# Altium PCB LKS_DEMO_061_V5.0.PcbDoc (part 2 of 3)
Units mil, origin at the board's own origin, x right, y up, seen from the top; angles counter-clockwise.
Board outline 4534.65 x 3225.59 mil, 2 copper layers (Top Layer, Bottom Layer); 196 components, 108 nets, 502 pads, 1380 vias.
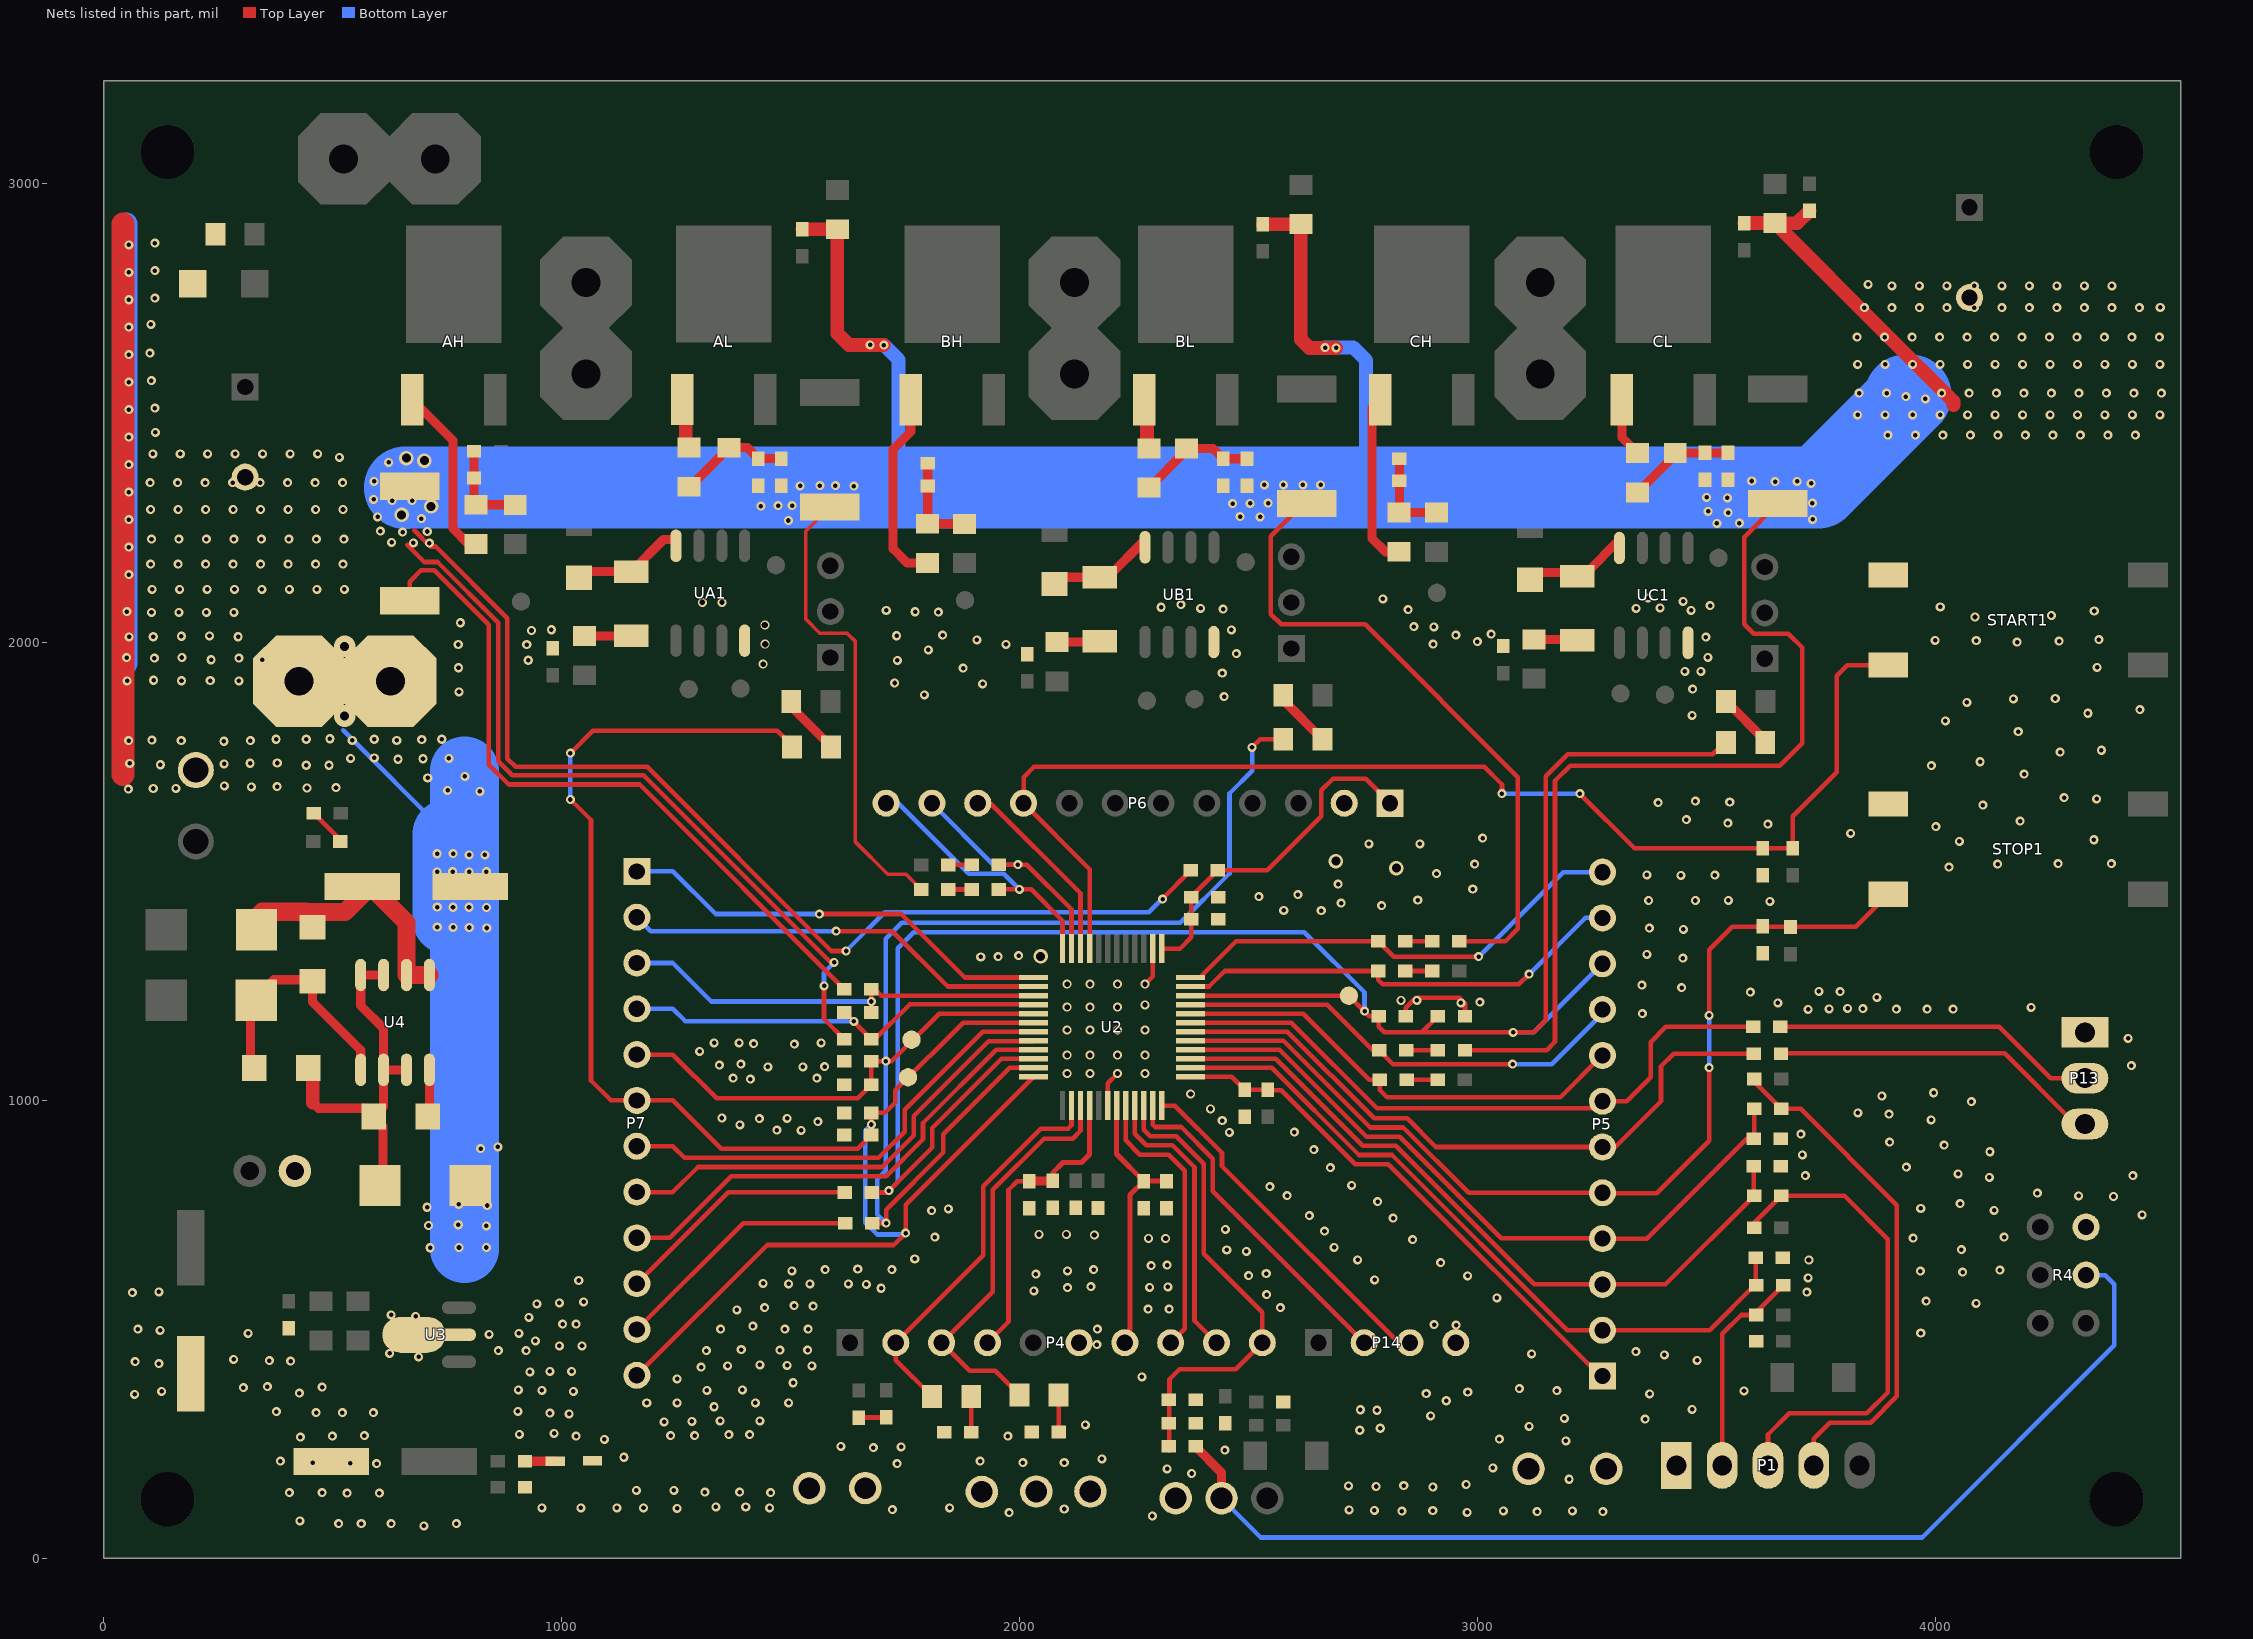
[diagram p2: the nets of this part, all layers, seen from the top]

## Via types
v1: diameter 19.68, hole 9.84, Top Layer to Bottom Layer, 1169 vias
v2: diameter 20, hole 10, Top Layer to Bottom Layer, 156 vias
v3: diameter 19.68, hole 11.81, Top Layer to Bottom Layer, 34 vias
v4: diameter 47.24, hole 20, Top Layer to Bottom Layer, 10 vias
v5: diameter 31.5, hole 19.68, Top Layer to Bottom Layer, 7 vias
v6: diameter 19.68, hole 13.78, Top Layer to Bottom Layer, 2 vias
v7: diameter 23.62, hole 11.81, Top Layer to Bottom Layer, 2 vias

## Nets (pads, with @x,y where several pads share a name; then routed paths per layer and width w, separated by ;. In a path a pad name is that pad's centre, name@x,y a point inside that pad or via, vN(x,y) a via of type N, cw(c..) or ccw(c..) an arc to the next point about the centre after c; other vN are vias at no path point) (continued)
GND: AGND.1 C1.2 C2.1 C3.2 C6.1 C12.2 C13.2 C14.2 C15.1 C17.1 C18.2 C19.1 C21.2 C22.1 C23.1 C25.1 C26.1 C27.1 C28.2 C29.2 C30.2 C31.2 C32.2 C33.2 C36.2 C37.1 C43.1 C44.1 C45.1 CA-5.1 CC3.2 CF1.2 D02.1 DM_IN.2 G1.1 G2.1 G3.1 G4.1 G5.1 G6.1 G7.1 G8.1 LED.2 P1.1 P4.6 P6.2 P13.1 P14.4 R4.2 R10.2 R14.2 R20.1 R43.1 R56.2 R58.2 R60.2 R69.2 R76.1 RA-5.2 RT-1.1 START1.1 STOP1.1 U2.6 U2.26 U3.2 UA1.4 UB1.4 UC1.4 | length 5737.3
  Top Layer w10: R69.2@668.11,2090.16 668.11,2132.05 692.99,2156.93 721.73,2156.93 840.94,2037.71 840.94,1732.28 884.25,1688.98 1170.55,1688.98 RT-1.1@1617.32,1242.2 ; RT-1.1@1619.29,1236.94 RT-1.1@1619.29,1251.26 ; R76.1@1648.43,307.31 C44.1@1709.05,307.31 ; U2.6@2191.84,988.17 2191.84,1036.6 v3(2213.41,1058.17) ; v3(2273.41,1253.17) 2290.26,1270.02 U2.26@2290.26,1330.69 ; P6.2@2708.41,1625.02 P6.2@2708.41,1648.17 ; R60.2@2842.91,1183.54 2842.91,1202.05 2864.57,1223.7 2960.16,1223.7 2972.05,1211.81 C18.2@2972.05,1183.07
  Top Layer w50: 42.52,1710.63 42.52,2912.97
  Bottom Layer w10: 523.23,1807.09 749.21,1581.1 ; P6.2@2702.41,1640.28 P6.2@2702.41,1654.17
  Bottom Layer w50: 49.61,1953.15 49.61,2912.4
  Bottom Layer w150: 749.21,1393.7 749.21,1581.1 ; 787.8,675.34 787.8,1719.17
  other v1: 699.21,70.87 512.99,75.59 562.6,75.59 627.95,75.59 770.47,75.59 428.74,81.5 1976.77,99.61 2976.77,100 3129.53,101.57 3272.83,101.57 3055.91,103.15 3206.69,103.15 2718.9,105.51 2774.41,104.72 1722.05,106.3 2097.24,107.48 1252.36,108.66 956.69,109.84 1042.13,109.84 1120.47,109.84 1178.74,109.84 1453.94,109.84 1846.85,109.84 1336.61,112.2 1401.97,112.2 531.89,142.13 601.97,142.13 405.91,143.31 477.17,143.31 1456.3,143.31 1312.6,144.49 1388.58,144.49 1163.39,148.03 1245.28,148.03 3199.61,172.44 2321.65,195.28 3033.07,197.24 596.06,206.3 538.98,207.48 1732.4,206.69 457.09,208.66 2007.09,208.66 2097.24,208.66 385.83,212.2 1913.39,212.2 2179.13,216.93 1135.83,220.47 2448.03,236.22 1680.71,241.73 1741.34,242.91 1609.45,244.09 3192.52,256.3 1093.31,259.45 3047.24,259.84 429.92,264.17 499.61,266.54 1031.5,266.54 1974.02,266.54 569.68,267.72 1238.19,267.72 1290.16,267.72 907.87,270.47 1364.96,270.08 1410.24,270.08 983.86,272.44 3112.2,287.8 2143.31,291.34 1223.62,297.64 1284.25,298.82 1346.06,300 1432.68,300 3365.35,303.54 3189.03,305.21 1016.14,315.35 974.41,316.54 464.17,317.72 521.26,317.72 588.98,317.72 377.56,320.08 904.72,320.47 3468.11,324.8 1333.07,330.71 1185.83,338.98 1252.36,338.98 1423.23,338.98 1495.67,338.98 67.72,357.87 3375.2,359.06 427.56,360.63 126.58,364.25 1025.59,364.17 3581.1,365.35 956.69,366.54 1317.32,366.54 3172.44,365.75 905.51,367.72 1394.49,367.72 3090.94,370.08 305.12,372.44 477.17,373.62 357.48,374.8 1505.12,383.07 1252.36,391.34 2266.93,396.06 930.71,406.69 974.41,407.87 1022.05,407.87 1304.33,417.32 1362.6,419.69 1546.46,419.69 1492.13,420.87 1432.68,422.05 120.83,424.62 68.9,429.13 408.27,430.31 362.2,431.5 3478.74,431.89 283.86,433.86 687.8,439.37 3407.09,444.09 3117.72,446.06 624.41,447.24 3344.88,450.79 861.81,453.15 922.44,453.15 1316.14,453.15 1476.38,454.33 1537.01,454.33 1392.13,455.51 994.88,463.78 1044.49,463.78 2168.5,466.14 942.52,474.41 841.73,488.58 315.75,490.94 906.69,490.94 3966.93,491.34 123.71,497.63 74.8,500.39 1347.24,500.39 1487.4,500.39 1538.19,500.39 2169.68,500.39 1417.32,506.69 2952.76,508.66 2904.72,509.84 1001.97,511.02 1031.5,511.02 928.35,525.59 681.5,527.95 627.95,531.5 1382.68,542.13 2280.31,543.7 2325.98,543.7 1443.31,546.85 2568.9,547.24 1548.82,550.39 1507.48,551.57 946.06,555.12 4087.8,556.3 994.88,557.48 1048.03,559.84 3978.74,561.02 3041.73,568.5 2538.98,575.59 62.99,579.92 120.83,581.57 3718.5,580.71 2030.71,583.46 1697.24,589.37 2104.33,590.55 2283.46,591.34 2323.23,592.13 2155.51,592.91 1665.35,597.64 1495.67,598.82 1541.73,598.82 1625.98,598.82 1439.76,600 1037.4,606.3 2774.8,607.87 3720.87,611.81 2977.95,616.54 2499.61,616.93 2035.43,620.47 2538.19,621.26 4058.27,624.8 1502.76,627.56 2104.33,627.56 3966.14,626.77 4139.76,628.74 1575.2,629.92 1720.87,629.92 2161.42,629.92 1646.46,631.1 2286.61,638.98 2321.65,639.76 2918.9,645.28 2737.4,651.18 1770.87,653.54 2494.88,669.69 2451.97,673.23 4055.51,673.62 2686.22,678.74 2857.87,695.67 3950.39,698.82 1814.96,701.18 4148.82,700.79 2665.35,714.17 2449.21,718.11 2815.35,742.52 2632.28,748.03 4449.99,749.41 1807.87,759.06 4127.17,759.45 1844.49,762.6 3966.93,763.78 4052.76,774.02 2781.1,778.35 4387.72,789.66 2583.86,791.34 4311.77,791.17 4221.4,797.25 2546.06,811.42 2724.41,814.17 4116.93,831.5 3714.96,835.43 4430.24,835.22 4048.43,838.98 2677.95,852.76 3935.83,853.54 3708.66,880.31 4117.85,887.37 2642.13,892.13 823.23,894.09 861.02,898.03 4018.11,901.97 3899.21,908.27 3705.12,925.59 2457.48,929.53 2599.61,930.31 1470.08,934.65 1522.83,933.86 1389.37,946.06 1559.45,953.15 2442.13,955.51 3989.36,957.1 1431.5,959.84 1492.52,960.24 1350,961.02 3897.64,969.69 3829.92,972.44 4077.56,996.85 3881.89,1009.06 3995.28,1016.14 1411.81,1046.06 1374.41,1048.03 1557.48,1048.03 1450,1072.44 1526.77,1072.44 1574.02,1073.23 4426.77,1075.59 1344.49,1076.38 1391.34,1078.74 1301.18,1106.69 1508.27,1122.44 1419.29,1123.62 1333.07,1124.8 1387.4,1124.8 1566.54,1124.8 4419.68,1135.04 3359.06,1188.98 3720.85,1197.99 3913.8,1198.51 3980.71,1198.51 4037.78,1198.55 3767.02,1199.03 3840.67,1199.55 3807.07,1200.12 4207.89,1202.66 2962.99,1212.6 3654.98,1212.52 3004.33,1214.17 2866.93,1217.72 3871.19,1224.3 3594.88,1235.83 3744.53,1237.43 3790.99,1236.72 3444.88,1245.67 3358.27,1251.18 3447.64,1309.84 1914.96,1312.99 1952.76,1313.39 1997.64,1315.35 3369.29,1318.11 3448.82,1372.83 3374.41,1375.59 2576.38,1414.17 2658.27,1413.78 2790.16,1424.8 2701.57,1430.31 3637.8,1433.86 2868.9,1436.61 3372.83,1435.83 3475.2,1435.83 3546.85,1436.22 2522.05,1444.09 2607.09,1448.43 2988.98,1460.63 2695.28,1471.65 3443.31,1490.55 3517.72,1491.34 3369.29,1491.73 2909.84,1494.49 728.47,1498.5 798.12,1498.32 762.2,1498.95 835.86,1498.95 4028.62,1508.49 2993.31,1515.35 4134.6,1515.43 4266.65,1516.31 4383.07,1516.14 798.27,1535.5 832.28,1535.43 728.19,1537.87 763.23,1538.24 2762.2,1559.45 2873.62,1559.45 3010.63,1572.05 3813.78,1582.28 3999.95,1597.1 3633.46,1602.76 3545.67,1604.72 4184.12,1609.26 3455.12,1612.2 4102.46,1644.01 3393.7,1649.61 3550,1650.79 3474.98,1652.75 4350.91,1657.91 4279.67,1660.51 750.96,1676.16 789.03,1706.67 4192.8,1711.76 3990.4,1730.01 4096.38,1738.7 4270.99,1759.55 54.75,1784.96 4179.78,1804.72 4020.8,1828.17 3468.11,1840.16 4445.55,1852.55 4067.71,1868.13 4169.35,1875.95 2446.06,1880.71 1792.13,1884.65 3468.9,1897.24 1918.9,1908.66 1726.77,1910.63 2442.13,1932.28 3451.97,1935.83 3487.01,1935.83 1876.38,1942.91 4352.05,1944.67 1733.07,1959.84 50.4,1965.95 3502.36,1966.54 2473.23,1974.8 1800.39,1982.68 1970.08,1994.88 2902.36,1995.28 2998.82,2001.18 4269.03,2002.25 3998.54,2003.89 1906.3,2004.72 4355.79,2005.53 55.71,2011.55 3497.64,2011.02 1731.5,2013.78 1831.89,2015.35 2952.36,2015.35 3029.13,2017.32 2461.81,2026.77 2904.33,2033.07 2860.24,2033.86 104.72,2064.96 164.72,2064.96 224.72,2064.96 284.72,2064.96 1822.44,2065.35 50.91,2066.28 1771.65,2066.14 1708.66,2069.29 3465.75,2069.29 2444.09,2071.65 2847.64,2070.87 2394.88,2073.62 3345.67,2073.62 3398.03,2074.41 2308.66,2075.98 3507.09,2079.53 2351.57,2081.5 3448.43,2088.98 2792.91,2094.09 3372.05,2096.46 105.91,2114.96 165.91,2114.96 225.91,2114.96 285.91,2114.96 345.91,2114.96 405.91,2114.96 465.91,2114.96 525.91,2114.96 55.51,2147.24 102.76,2170.08 162.76,2170.08 222.76,2170.08 282.76,2170.08 342.76,2170.08 402.76,2170.08 462.76,2170.08 522.76,2170.08 55.51,2207.24 104.72,2224.8 164.72,2224.8 224.72,2224.8 284.72,2224.8 344.72,2224.8 404.72,2224.8 464.72,2224.8 524.72,2224.8 55.51,2267.24 102.76,2289.37 162.76,2289.37 222.76,2289.37 282.76,2289.37 342.76,2289.37 402.76,2289.37 462.76,2289.37 522.76,2289.37 55.51,2327.24 101.97,2348.03 161.97,2348.03 221.97,2348.03 281.97,2348.03 341.97,2348.03 401.97,2348.03 461.97,2348.03 521.97,2348.03 55.51,2387.24 514.96,2403.15 107.48,2410.63 167.48,2410.63 227.48,2410.63 287.48,2410.63 347.48,2410.63 407.48,2410.63 467.48,2410.63 55.51,2447.24 112.99,2457.48 55.51,2507.24 112.2,2510.71 55.51,2567.24 104.38,2570.53 55.51,2627.24 101.44,2630.72 55.51,2687.24 103.47,2693.4 55.51,2747.24 112.2,2750.71 55.51,2807.24 112.2,2810.71 55.51,2867.24 112.2,2870.71
  other v2: 2289.76,92.13 2834.25,102.76 2901.57,103.94 2901.97,155.51 2777.95,156.69 2717.72,157.87 2838.19,158.66 2974.41,161.02 2375.2,185.04 2742.13,279.53 2787.01,283.86 2896.85,310.63 2779.92,323.23 2743.7,324.02 2931.1,343.7 2887.4,359.45 2977.95,362.6 712.99,677.95 775.98,678.35 835.83,678.35 835.83,725.59 709.45,726.38 774.41,727.95 706.3,766.14 837.8,770.08 775.59,772.83 836.59,1375.81 763.23,1377.1 798.45,1376.91 728.56,1377.82 836.05,1420.53 728.38,1421.44 762.87,1421.26 797.9,1421.07 4051.2,1564.95 4344.83,1568.43 821.66,1674.05 54.39,1678.91 108.42,1680.3 157.92,1680.65 444.09,1681.5 507.48,1682.28 322.8,1683.79 378.92,1684.48 263.89,1685.88 707.76,1703.35 442.52,1731.1 492.13,1731.1 124.1,1732.24 263.19,1733.99 57.18,1735.03 320.01,1735.37 379.27,1736.07 642.81,1744.14 697.49,1745.35 539.37,1746.06 753.98,1745.95 590.94,1747.24 4361.34,1763.89 262.84,1783.48 169.77,1784.88 320.71,1784.88 542.91,1785.43 640.16,1785.43 105.64,1785.92 694.77,1787.04 376.77,1787.8 442.52,1787.8 590.94,1787.8 738.27,1787.94 494.09,1788.98 4331.8,1844.68 4260.56,1876.82 775.96,1891.09 51.52,1915.15 170.3,1915.52 295.44,1915.15 109.41,1916.64 233.05,1915.89 774.95,1943.93 927.17,1960.24 234.92,1961.47 346.46,1961.81 110.91,1964.83 295.44,1964.83 171.05,1966.32 924.02,1994.49 774.44,1994.74 4177.37,1999.8 4088.16,2003.07 108.52,2011.55 293.82,2011.55 169.97,2012.51 231.42,2013.47 934.25,2025.2 977.56,2026.77 779.01,2041.99 4085.29,2054.63 4252.26,2057.91 4345.56,2067.73 4009.59,2076.73
  other v3: 3722.6,651.06 2281.1,698.43 2318.5,698.03 2162.99,705.59 2042.13,707.17 2101.97,707.17 2416.54,981.1 2373.23,1013.39 2103.41,1058.17 2153.41,1058.17 2273.41,1058.17 2103.41,1098.17 2153.41,1098.17 2213.41,1098.17 2273.41,1098.17 2103.41,1153.17 2153.41,1153.17 2213.41,1153.17 2273.41,1153.17 2103.41,1203.17 2153.41,1203.17 2213.41,1203.17 2273.41,1208.17 2832.28,1217.72 2103.41,1253.17 2153.41,1253.17 2213.41,1253.17 1439.76,1951.57 1307.11,2086.72 1350.11,2086.72
  other v4: 526.38,1838.57 526.38,1990.57
  other v5: 2045.67,1313.78 2822.05,1506.3 2690.16,1521.65
  other v6: 1444.49,1995.28 1443.7,2037.4
HALL_A: C31.1 P5.4 R54.2 U2.16 | length 1555.5
  Top Layer w10: U2.16@2372.94,1110.22 2567.15,1110.22 2757.14,920.24 2829.26,920.24 3051.07,698.43 3271.34,698.43 P5.4@3272.05,697.72 3368.47,697.72 3586.81,916.06 C31.1@3602.6,916.06 ; C31.1@3603.07,916.54 R54.2@3603.07,981.06
HALL_B: C32.1 P5.3 R57.2 U2.15 | length 1578.9
  Top Layer w10: U2.15@2372.94,1090.54 2558.55,1090.54 2748.85,900.24 2820.98,900.24 3123.5,597.72 P5.3@3272.05,597.72 3409.72,597.72 R57.2@3603.07,791.06 ; R57.2@3602.6,791.54 C32.1@3602.6,856.06
HALL_C: C33.1 P5.2 R62.2 U2.14 | length 1570.5
  Top Layer w10: U2.14@2372.94,1070.85 2549.95,1070.85 2740.57,880.24 2812.69,880.24 3195.21,497.72 P5.2@3272.05,497.72 3506.18,497.72 3606.3,597.83 C33.1@3606.3,656.06
LDO15: C27.2 C28.1 P4.7 U2.7 | length 604.3
  Top Layer w11: U2.7@2211.52,988.17 2211.52,882.58 C27.2@2270.87,823.23 ; P4.7@2240.94,470.47 2240.94,793.31 C27.2@2270.87,823.23 ; C28.1@2320.47,823.23 C27.2@2270.87,823.23
LDO33: C29.1 C30.1 P4.4 U2.4 | length 678.5
  Top Layer w10: P4.4@1929.53,470.47 1975.59,516.54 1975.59,803.94 1994.91,823.25 C29.1@2020.58,823.25
  Top Layer w11: C30.1@2072.44,824.02 2072.44,841.73 2094.49,863.78 2135.04,863.78 2152.47,881.21 U2.4@2152.47,988.17
  Top Layer w20: C29.1@2020.58,823.25 C30.1@2072.44,823.25
LED2: L2.1 P4.2 U2.2 | length 861
  Top Layer w10: L2.1@1808.43,353.51 1729.53,432.41 P4.2@1729.53,470.47 1920.47,661.42 1920.47,811.81 2046.06,937.4 2105.51,937.4 2113.1,944.99 U2.2@2113.1,988.17
LED3: L1.1 P4.3 U2.3 | length 897.4
  Top Layer w10: L1.1@1999.41,356.29 1946.25,409.45 1890.55,409.45 P4.3@1829.53,470.47 1940.94,581.89 1940.94,804 2053.09,916.14 2116.14,916.14 2132.78,932.78 U2.3@2132.78,988.17
LKS_PIN7: P6.10 U2.34 | length 426.6
  Top Layer w10: P6.10@1908.41,1648.17 1936.08,1648.17 2132.78,1451.47 U2.34@2132.78,1330.69
LKS_PIN8: P7.1 U2.37 | length 962.1
  Top Layer w10: v1(1562.6,1406.3) 1741.34,1406.3 1879.94,1267.7 U2.37@2030.42,1267.7
  Bottom Layer w10: P7.1@1164.25,1499.39 1242.99,1499.39 1336.09,1406.3 v1(1562.6,1406.3)
LKS_PIN10: P4.9 U2.9 | length 625.4
  Top Layer w10: U2.9@2250.89,988.17 2250.89,926.28 2275.91,901.26 2333.45,901.26 2381.5,853.21 2381.5,518.5 P4.9@2429.53,470.47
LKS_PIN11: P4.8 U2.8 | length 620.8
  Top Layer w10: U2.8@2231.21,988.17 2231.21,912.2 2262.31,881.1 2325.32,881.1 2360.24,846.19 2360.24,501.18 P4.8@2329.53,470.47
NetAH_1: AH.1 K1.2 | length 382.5
  Top Layer w20: AH.1@673.62,2529.13 762.6,2440.16 762.6,2248.03 796.65,2213.98 K1.2@812.99,2213.98
NetAL_1: AL.1 K2.2 | length 112.7
  Top Layer w20: AL.1@1258.27,2529.13 AL.1@1270.87,2516.54
  Top Layer w30: AL.1@1270.87,2516.54 1270.87,2431.69 K2.2@1277.95,2424.61
NetBH_1: BH.1 K3.2 | length 429.6
  Top Layer w20: BH.1@1762.2,2529.13 1762.2,2459.45 1723.62,2420.87 1723.62,2203.54 1754.53,2172.64 K3.2@1798.82,2172.64
NetBL_1: BL.1 K4.2 | length 67.8
  Top Layer w30: K4.2@2277.95,2422 BL.1@2277.95,2489.76
NetC7_1: C7.1 K1.1 K+A1.2 R21.2 | length 204.2
  Top Layer w20: C7.1@808.72,2358.14 R21.2@808.66,2416.14 ; C7.1@808.72,2358.14 808.72,2303.88 K1.1@812.99,2299.61 898.62,2299.61 K+A1.2@898.82,2299.41
NetC11_1: C11.1 K2.1 K-A1.1 R31.2 | length 246.9
  Top Layer w20: K2.1@1277.95,2338.98 1280.31,2338.98 K-A1.1@1365.35,2424.02 ; K-A1.1@1365.35,2424.8 1405.23,2424.8 R31.2@1429.56,2400.47 1429.64,2400.39 C11.1@1479.53,2400.39
NetC16_1: C16.1 K3.1 K+B1.2 R39.2 | length 212.8
  Top Layer w20: R39.2@1799.21,2390.16 1799.21,2258.66 K3.1@1798.82,2258.27 1879.33,2258.27 K+B1.2@1879.53,2258.07
NetC20_1: C20.1 K4.1 K-B1.1 R45.2 | length 261.3
  Top Layer w20: K4.1@2282.39,2337.06 2364.17,2418.84 K-B1.1@2364.17,2422.83 2421.65,2422.83 R45.2@2444.49,2400 2496.12,2400 C20.1@2496.28,2399.84
NetC24_1: C24.1 K5.1 K+C1.2 R50.2 | length 200
  Top Layer w20: R50.2@2828.74,2400 2828.74,2283.46 K5.1@2827.95,2282.68 2828.15,2282.48 K+C1.2@2910.24,2282.48
NetC34_1: C34.1 K6.1 K-C1.1 R63.2 | length 232.8
  Top Layer w20: K6.1@3349.02,2326.73 3435.33,2413.05 C34.1@3546.09,2413.05
NetCAH1_1: CAH1.1 D1.2 UA1.8 | length 240.8
  Top Layer w20: CAH1.1@1037.8,2153.94 1151.39,2153.94 D1.2@1151.93,2153.4 1222.45,2223.93 UA1.8@1249.14,2223.93
NetCBH1_1: CBH1.1 D2.2 UB1.8 | length 230.6
  Top Layer w20: CBH1.1@2076.77,2141.34 2192.21,2141.34 UB1.8@2273.62,2222.75
NetCCH1_1: CCH1.1 D4.2 UC1.8 | length 225.3
  Top Layer w20: CCH1.1@3113.39,2151.57 3237.49,2151.57 UC1.8@3309.06,2223.14
NetCF1_1: CF1.1 DD6.2 RP1.2 U4.5 U4.6 | length 567.4
  Top Layer w40: DD6.2@321.98,1386.47 346.53,1411.02 440.94,1411.02 ; 441.34,1410.63 527.17,1410.63 582.68,1466.14 661.42,1387.4 ; 661.42,1385.74 U4.6@661.42,1273.14 U4.5@711.42,1273.14
NetCF2_1: CF2.1 DP1.2 RP1.1 U4.1 | length 538
  Top Layer w20: CF2.1@320.8,1067.05 320.8,1211.6 372,1262.8 RP1.1@455.94,1262.8 ; RP1.1@455.84,1259.49 455.84,1214.65 561.42,1109.07 U4.1@561.42,1066.14
NetCF2_2: CF2.2 D02.2 PL1.2 RP2.2 U4.2 U4.3 U4.7 U4.8 | length 756.1
  Top Layer w20: 456.98,994.57 469.27,982.28 RP2.2@569.69,982.28 ; D02.2@609.77,849.61 609.77,942.2 588.58,963.38 611.42,986.22 U4.2@611.42,1066.14 ; U4.7@611.42,1273.14 U4.8@561.42,1273.14 561.42,1206.3 611.42,1156.3 U4.2@611.42,1066.14 ; U4.3@661.42,1066.14 U4.2@611.42,1066.14
  Top Layer w30: 456.98,994.57 CF2.2@456.98,1070.33
NetCH_1: CH.1 K5.2 | length 381.2
  Top Layer w20: CH.1@2787.01,2529.13 2768.9,2511.02 2768.9,2226.77 2798.62,2197.05 K5.2@2827.95,2197.05
NetCL_1: CL.1 K6.2 | length 131
  Top Layer w20: CL.1@3314.57,2529.13 3314.57,2446.81 K6.2@3349.02,2412.36
NetD1_1: D1.1 R79.2 | length 102
  Top Layer w20: R79.2@1050,2013.19 1151.71,2013.19 D1.1@1151.93,2013.4
NetD2_1: D2.1 R78.2 | length 94.2
  Top Layer w20: R78.2@2081.5,1999.8 2173.09,1999.8 D2.1@2174.95,2001.66
NetD4_1: D4.1 R77.2 | length 96.7
  Top Layer w20: R77.2@3122.83,2005.71 D4.1@3219.33,2005.71 ; D4.1@3219.72,2017.91 D4.1@3219.83,2017.8
NetL1_2: L1.2 R14.1 | length 80.9
  Top Layer w10: L1.2@2085.04,356.29 2085.04,275.98 R14.1@2085.43,275.59
NetL2_2: L2.2 R10.1 | length 78.3
  Top Layer w10: L2.2@1894.06,353.51 1894.06,275.24 R10.1@1894.09,275.2
NetLED_1: LED.1 R65.2 | length 65.9
  Top Layer w20: R65.2@920.08,211.81 LED.1@986.02,211.81
NetP1_2: P1.2 R51.1 R62.1 | length 468.2
  Top Layer w10: P1.2@3533.46,202.76 3533.46,489.76 3574.76,531.06 R51.1@3608.07,531.06 3608.07,537.01 R62.1@3667.13,596.06
NetP1_3: P1.3 R52.1 R57.1 | length 1067.9
  Top Layer w10: R52.1@3603.07,721.06 3603.07,732.01 R57.1@3662.13,791.06 3800.39,791.06 3894.88,696.57 3894.88,361.81 3849.21,316.14 3679.53,316.14 3633.46,270.08 P1.3@3633.46,202.76
NetP1_4: P1.4 R53.1 R54.1 | length 1124.7
  Top Layer w10: R53.1@3603.07,1046.06 3603.07,1040.12 R54.1@3662.13,981.06 3704.76,981.06 3914.88,770.94 3914.88,353.53 3857.5,296.14 3768.5,296.14 3733.46,261.1 P1.4@3733.46,202.76
NetP13_2: P13.2 R12.1 | length 710.9
  Top Layer w10: R12.1@3660.63,1159.84 4138.71,1159.84 4250.52,1048.03 P13.2@4325.2,1048.03
NetP13_3: P13.3 R9.2 | length 726.1
  Top Layer w10: R9.2@3661.81,1102.36 4150,1102.36 4304.33,948.03 P13.3@4324.02,948.03
NetR1_1: R1.1 R55.2 | length 134.9
  Top Layer w20: R1.1@1501.18,1870.08 1501.18,1858.46 R55.2@1588.39,1771.26
NetR2_1: R2.1 R59.2 | length 131.5
  Top Layer w20: R2.1@2575.2,1883.86 2575.2,1873.43 R59.2@2660.83,1787.8
NetR3_1: R3.1 R61.2 | length 124.7
  Top Layer w20: R3.1@3542.13,1870.47 3627.36,1785.24 R61.2@3627.36,1781.1
NetR74_2: R74.2 R75.1 | length 85.9
  Top Layer w10: R75.1@458.66,1626.38 516.93,1568.11 R74.2@516.93,1564.57
NetRP2_1: RP2.1 U4.4 | length 101.6
  Top Layer w20: RP2.1@711.42,964.56 U4.4@711.42,1066.14
NetRPA1_1: RPA1.1 RPA2.2 | length 51.2
  Top Layer w10: RPA2.2@1843.7,1513.78 RPA1.1@1894.88,1513.78
NetRPA3_1: RPA3.1 RPA4.2 | length 51.2
  Top Layer w10: RPA4.2@1843.7,1459.84 RPA3.1@1894.88,1459.84
NetRPB1_1: RPB1.1 RPB2.2 | length 59.1
  Top Layer w10: RPB1.1@2841.73,1281.97 RPB2.2@2900.79,1281.97
NetRPB3_1: RPB3.1 RPB4.2 | length 59.1
  Top Layer w10: RPB3.1@2841.73,1346.93 RPB4.2@2900.79,1346.93
NetRPC1_1: RPC1.1 RPC2.2 | length 67.5
  Top Layer w10: RPC1.1@2844.88,1044.49 2911.81,1044.49 RPC2.2@2912.2,1044.88
NetRPC3_1: RPC3.1 RPC4.2 | length 69.3
  Top Layer w10: RPC3.1@2843.7,1109.06 RPC4.2@2912.99,1109.06
NRST: C21.1 P5.1 R48.1 U2.13 | length 1164.7
  Top Layer w10: U2.13@2372.94,1051.17 2462.78,1051.17 C21.1@2491.56,1022.39 R48.1@2541.73,1022.39 2551.09,1022.39 2551.56,1021.91 2570.61,1021.91 2732.28,860.24 2804.41,860.24 P5.1@3266.93,397.72
OC: C17.2 P6.1 R20.2 R38.1 U2.25 | length 758.8
  Top Layer w10: U2.25@2309.94,1330.69 2349.98,1330.69 2374.8,1355.51 R20.2@2374.8,1395.28 C17.2@2374.8,1442.52 2374.8,1443.7 R38.1@2432.68,1501.57 2540.08,1501.57 2658.66,1620.16 2658.66,1676.46 2683.78,1701.57 2755.01,1701.57 P6.1@2808.41,1648.17
OPA1_IN: P5.9 RPC3.2 U2.21 | length 1007.3
  Top Layer w10: U2.21@2372.94,1208.65 2671.26,1208.65 2770.85,1109.06 RPC3.2@2784.65,1109.06 2814.96,1078.74 v1(3075.98,1078.74)
  Bottom Layer w10: v1(3075.98,1078.74) 3161.81,1078.74 3272.05,1188.98 P5.9@3272.05,1197.72
OPA1_IP: P5.8 RPC1.2 U2.20 | length 1026.1
  Top Layer w10: U2.20@2372.94,1188.96 2618.91,1188.96 2763.39,1044.49 RPC1.2@2785.83,1044.49 2785.83,1022.05 2801.97,1005.91 3180.24,1005.91 P5.8@3272.05,1097.72
OPA2_IN: P5.12 RPB3.2 U2.24 | length 1022.2
  Top Layer w10: U2.24@2372.94,1267.7 2392.94,1267.7 2472.17,1346.93 RPB3.2@2782.68,1346.93 2816.22,1313.39 v1(3001.97,1313.39)
  Bottom Layer w10: v1(3001.97,1313.39) 3186.3,1497.72 P5.12@3272.05,1497.72
OPA2_IP: P5.11 RPB1.2 U2.23 | length 1003.6
  Top Layer w10: U2.23@2372.94,1248.02 2413.25,1248.02 2447.2,1281.97 RPB1.2@2782.68,1281.97 ; RPB1.2@2789.37,1281.97 RPB1.2@2782.68,1281.97 ; v1(3112.2,1275.2) 3089.76,1252.76 2792.13,1252.76 2782.68,1262.2 RPB1.2@2782.68,1281.97
  Bottom Layer w10: v1(3112.2,1275.2) 3234.72,1397.72 P5.11@3272.05,1397.72
OPA3_IN: P6.12 RPA3.2 U2.36 | length 597.5
  Top Layer w10: RPA3.2@1953.94,1460.24 v1(1999.21,1460.24) 2024.8,1460.24 2093.41,1391.63 U2.36@2093.41,1330.69
  Bottom Layer w10: P6.12@1708.41,1648.17 1734.5,1648.17 1888.5,1494.17 1965.28,1494.17 v1(1999.21,1460.24)
OPA3_IP: P6.11 RPA1.2 U2.35 | length 525
  Top Layer w10: RPA1.2@1953.94,1514.17 v1@1992.52,1514.17 ; v1(1996.06,1514.17) 2015.35,1514.17 2113.09,1416.43 U2.35@2113.09,1330.69
  Bottom Layer w10: P6.11@1808.41,1648.17 1942.41,1514.17 v1(1996.06,1514.17)
OPA4_IN: CT1.2 P7.3 RT-1.2 U2.39 | length 971.5
  Top Layer w10: CT1.2@1675.54,1191.34 RT-1.2@1675.54,1243.04 ; RT-1.2@1676.38,1242.2 RT-1.2@1675.54,1243.04 ; U2.39@2030.42,1228.33 1698.13,1228.33 1675.54,1250.91 RT-1.2@1675.54,1243.04
  Bottom Layer w10: P7.3@1164.25,1299.39 1242.99,1299.39 1327.03,1215.35 v1(1675.98,1215.35)
OPA4_IP: CT1.1 P7.4 RT+1.2 U2.40 | length 955.1
  Top Layer w10: CT1.1@1616.54,1191.34 1617.79,1191.34 RT+1.2@1675.94,1133.19 1676.46,1132.66 1683.84,1132.66 1760.09,1208.91 2030.16,1208.91 U2.40@2030.42,1208.65
  Bottom Layer w10: P7.4@1164.25,1199.39 1242.99,1199.39 1270.34,1172.05 v1(1638.19,1172.05)
PA: C13.1 P7.6 P7.12 R55.1 R56.1 T1.1 U2.42 U2.48 | length 3927.9
  Top Layer w10: v1(1019.29,1656.3) 1064.11,1611.48 1064.11,1042.98 1107.69,999.39 P7.6@1164.25,999.39 1242.99,999.39 1348.29,894.09 1646.06,894.09 C13.1@1675.98,924.02 R56.1@1675.98,972.05 1705.51,972.05 1728.35,994.88 1728.35,1021.26 1876.36,1169.28 U2.42@2030.42,1169.28 ; v1(1019.29,1757.48) 1067.95,1806.14 1470.63,1806.14 R55.1@1502.36,1774.41 ; P7.12@1164.25,399.39 1448.72,683.86 1725.2,683.86 v1(1751.18,709.84) 1751.18,771.93 U2.48@2030.42,1051.17
  Bottom Layer w10: v1(1019.29,1656.3) v1(1019.29,1757.48) ; v1(1675.98,946.85) 1662.6,933.46 1662.6,732.68 1688.62,706.65 1747.99,706.65 v1(1751.18,709.84)
PB: C14.1 P7.5 R11.2 R58.1 R59.1 T2.1 U2.41 U2.47 | length 3365.4
  Top Layer w10: P7.5@1164.25,1099.39 1242.99,1099.39 1338.45,1003.94 1646.06,1003.94 C14.1@1675.98,1033.86 ; C14.1@1675.98,1033.86 R58.1@1675.98,1085.04 1720.08,1085.04 1824,1188.96 U2.41@2030.42,1188.96 ; R11.2@1677.95,731.5 v1(1708.27,731.5) 1708.27,760.93 1833.07,885.73 1833.07,925.59 1978.33,1070.85 U2.47@2030.42,1070.85 ; v1(2507.09,1770.08) 2524.8,1787.8 R59.1@2575.2,1787.8
  Bottom Layer w10: v1(1708.27,731.5) 1689.37,750.39 1689.37,827.95 1707.87,846.46 v1(1707.87,1085.04) 1707.87,1352.64 1742.64,1387.4 2350.64,1387.4 2457.94,1494.7 2457.94,1669.42 2507.87,1719.35 v1@2507.87,1772.44
PC: C18.1 P5.10 R8.1 R60.1 R61.1 T3.1 U2.22 U2.46 | length 4261.5
  Top Layer w10: R8.1@1677.17,798.43 1710.63,798.43 v1(1714.57,802.36) 1808.82,896.61 1808.82,939.13 1960.22,1090.54 U2.46@2030.42,1090.54 ; U2.22@2372.94,1228.33 T3.1@2718.5,1228.33 ; T3.1@2718.5,1227.95 2762.91,1183.54 R60.1@2783.86,1183.54 2783.86,1160.24 2796.06,1148.03 2877.95,1148.03 ; C18.1@2912.99,1183.07 2877.95,1148.03 ; R61.1@3541.73,1781.1 3538.98,1781.1 3512.99,1755.12 3196.46,1755.12 3148.5,1707.17 3148.5,1174.09 3122.44,1148.03 v1(3077.17,1148.03) 2877.95,1148.03
  Bottom Layer w10: v1(1714.57,802.36) 1733.46,821.26 1733.46,1331.18 1768.9,1366.61 2621.46,1366.61 2752.76,1235.32 v1(2752.76,1194.49) ; v1(3077.17,1148.03) 3122.36,1148.03 P5.10@3272.05,1297.72
PGND: C11.2 C20.2 C34.2 CA.1 CB.1 CC1.2 CC.1 R15.2 R16.1 R17.2 R31.1 R38.2 R45.1 R49.2 R63.1 R69.1 RA1.1 RB1.1 RC1.1 RPA4.1 RPB4.1 RPC4.1 RT+1.1 | length 14170.5
  Top Layer w8: R15.2@1585.04,2294.49 1532.68,2242.13 1532.68,2050.39 1563.78,2019.29 1623.23,2019.29 1641.34,2001.18 1641.34,1563.78 1712.2,1492.91 1751.97,1492.91 RPA4.1@1785.04,1459.84
  Top Layer w10: 662.6,2212.6 700.39,2174.8 729.13,2174.8 861.81,2042.13 861.81,1739.7 892.54,1708.98 1178.84,1708.98 1587.22,1300.59 v1(1595.08,1300.59) ; 677.95,2243.7 712.99,2208.66 725.2,2208.66 881.5,2052.36 881.5,1745.67 899.61,1727.56 1186.61,1727.56 1588.58,1325.59 v1(1620.87,1325.59) ; v1(1572.83,1249.61) 1572.83,1177.24 RT+1.1@1616.88,1133.19 ; v1(2311.81,1438.98) 2311.81,1439.76 R38.2@2373.62,1501.57 ; R16.1@2626.38,2302.36 2620.08,2302.36 2548.39,2230.67 2548.39,2061.06 2570.87,2038.58 2753.94,2038.58 3087.4,1705.12 3087.4,1373.95 3060.38,1346.93 RPB4.1@2959.84,1346.93 ; RPC4.1@2972.05,1109.06 3150.46,1109.06 3168.5,1127.1 3168.5,1696.93 3201.65,1730.08 3658.82,1730.08 3707.95,1779.21 3707.95,1988.17 3677.62,2018.5 3601.97,2018.5 3581.85,2038.62 3581.85,2229.1 R17.2@3655.12,2302.36
  Top Layer w30: RA1.1@1525.59,2901.18 CA.1@1601.97,2901.18 1601.97,2673.62 1627.17,2648.43 v1(1703.43,2648.43) ; RB1.1@2530.76,2912.28 CB.1@2613.76,2912.28 2613.76,2660.65 2632.3,2642.11 v1(2690.55,2642.11) ; RC1.1@3581.89,2914.57 3648.91,2914.57 CC.1@3649.01,2914.46 ; R49.2@3724.02,2941.34 3697.14,2914.46 CC.1@3649.01,2914.46 ; 4038.58,2517.72 4038.58,2524.89 3892.84,2670.63 CC.1@3649.01,2914.46
  Bottom Layer w10: v1(1572.83,1249.61) 1572.83,1278.35 v1(1595.08,1300.59) ; v1(1620.87,1325.59) 1705.12,1409.84 2281.5,1409.84 v1@2311.12,1439.46
  Bottom Layer w30: 1658.66,2337.43 1735.43,2414.2 1735.43,2616.42 v1(1703.43,2648.43) 1703.03,2648.82 v1(1673.62,2648.82) ; v1(2666.54,2642.91) 2728.35,2642.91 2755.91,2615.35 2755.91,2388.22 2705.12,2337.43
  Bottom Layer w180: 658.28,2337.02 681.51,2337.43 714.98,2337.43 1435.04,2337.43 1597.64,2337.43 1658.66,2337.43 2534.25,2337.43 2575.59,2337.43 2705.12,2337.43 3521.65,2337.43 3546.46,2337.43 3648.82,2337.43 3727.56,2337.43 3731.1,2337.43 3742.94,2337.43 3943.7,2538.19 v1@3934.65,2538.19
  other v1: 676.38,2216.54 711.42,2216.14 629.13,2217.72 652.76,2240.16 706.69,2241.34 604.33,2242.13 3521.65,2259.06 3571.26,2259.84 1494.88,2265.35 3731.1,2267.72 693.7,2269.29 598.43,2273.23 2524.8,2273.23 2481.1,2274.02 3546.46,2282.68 3502.76,2285.43 1435.04,2296.85 1472.83,2298.03 1503.15,2298.03 2464.96,2302.36 2502.76,2302.76 2542.13,2303.15 3730.31,2303.54 629.92,2308.66 673.62,2308.66 589.37,2311.42 3544.88,2314.96 3499.61,2315.75 1637.8,2340.16 1520.87,2340.94 1563.78,2341.34 1597.64,2341.34 2534.25,2342.91 2575.59,2343.31 2618.11,2342.91 2656.69,2343.31 3727.56,2346.46 3648.82,2350 590.55,2350.79 3598.03,2351.57 3697.24,2350.79 622.44,2392.13 3895.28,2451.57 3955.28,2451.57 4015.28,2451.57 4075.28,2451.57 4135.28,2451.57 4195.28,2451.57 4255.28,2451.57 4315.28,2451.57 4375.28,2451.57 4435.28,2451.57 3829.13,2495.67 3889.13,2495.67 3949.13,2495.67 4009.13,2495.67 4069.13,2495.67 4129.13,2495.67 4189.13,2495.67 4249.13,2495.67 4309.13,2495.67 4369.13,2495.67 4429.13,2495.67 4489.13,2495.67 3977.17,2530.71 3934.65,2535.83 3832.28,2543.31 3892.28,2543.31 4012.28,2543.31 4072.28,2543.31 4132.28,2543.31 4192.28,2543.31 4252.28,2543.31 4312.28,2543.31 4372.28,2543.31 4432.28,2543.31 4492.28,2543.31 3829.13,2606.3 3889.13,2606.3 3949.13,2606.3 4009.13,2606.3 4069.13,2606.3 4129.13,2606.3 4189.13,2606.3 4249.13,2606.3 4309.13,2606.3 4369.13,2606.3 4429.13,2606.3 4489.13,2606.3 3827.95,2665.75 3887.95,2665.75 3947.95,2665.75 4007.95,2665.75 4067.95,2665.75 4127.95,2665.75 4187.95,2665.75 4247.95,2665.75 4307.95,2665.75 4367.95,2665.75 4427.95,2665.75 4487.95,2665.75 3844.09,2730.32 3904.09,2730.32 3964.09,2730.32 4024.09,2730.32 4084.09,2730.32 4144.09,2730.32 4204.09,2730.32 4264.09,2730.32 4324.09,2730.32 4384.09,2730.32 4444.09,2730.32 4489.76,2730.71 3904.09,2777.56 3964.09,2777.56 4024.09,2777.56 4084.09,2777.56 4144.09,2777.56 4204.09,2777.56 4264.09,2777.56 4324.09,2777.56 4384.09,2777.56 3851.97,2780.71
  other v5: 650.8,2277.5 714.98,2296.39 700.41,2396 661.04,2401.51
PIN38: P7.2 U2.38 | length 928.9
  Top Layer w10: v1(1599.21,1368.9) 1722.05,1368.9 1842.93,1248.02 U2.38@2030.42,1248.02
  Bottom Layer w10: P7.2@1164.25,1399.39 1194.75,1368.9 v1(1599.21,1368.9)
PIN43: P7.7 U2.43 | length 1019
  Top Layer w10: P7.7@1164.25,899.39 1242.99,899.39 1268.37,874.02 1691.73,874.02 1748.82,931.1 1748.82,979.13 1919.28,1149.59 U2.43@2030.42,1149.59
PIN44: P7.8 U2.44 | length 1027.9
  Top Layer w10: P7.8@1164.25,799.39 1242.99,799.39 1297.61,854.02 1700.02,854.02 1768.82,922.82 1768.82,965.28 1932.54,1129 2029.51,1129 U2.44@2030.42,1129.91
PIN45: P7.9 U2.45 | length 1057.2
  Top Layer w10: P7.9@1164.25,699.39 1235.97,699.39 1370.59,834.02 1708.3,834.02 1788.82,914.53 1788.82,950.24 1948.8,1110.22 U2.45@2030.42,1110.22
RXD0: P5.6 R9.1 U2.18 | length 1463.3
  Top Layer w10: U2.18@2372.94,1149.59 2584.35,1149.59 2773.7,960.24 2845.83,960.24 2908.35,897.72 P5.6@3272.05,897.72 3300.08,897.72 3400,997.64 3400,1074.02 3427.56,1101.57 R9.1@3602.76,1101.57
RXD1: P7.10 R8.2 | length 536.9
  Top Layer w10: P7.10@1164.25,599.39 1363.99,799.13 1617.4,799.13 R8.2@1618.11,798.43
SPIN: C19.2 P4.10 R42.2 R43.2 U2.10 | length 1067.9
  Top Layer w10: U2.10@2270.58,988.17 2270.58,935.43 2284.75,921.26 2341.73,921.26 2401.5,861.5 2401.5,665.01 2529.53,536.98 P4.10@2529.53,470.47 2471.65,412.6 2348.82,412.6 2327.05,390.83 2327.05,347.52 C19.2@2326.72,347.2 ; R42.2@2326.72,234.49 C19.2@2326.72,347.2 ; C19.2@2326.72,347.2 C19.2@2325.2,345.67 2326.77,354.06 2326.72,354.02 C19.2@2326.72,347.2
START1: C3.1 P6.9 R13.1 START1.2 U2.33 | length 2746.5
  Top Layer w10: U2.33@2152.46,1330.69 2152.46,1504.12 P6.9@2008.41,1648.17 2008.41,1704.87 2031.1,1727.56 3014.17,1727.56 3052.76,1688.98 v1(3052.76,1668.9) ; v1(3222.83,1668.9) 3342.05,1549.68 C3.1@3622.44,1549.68 R13.1@3687.87,1549.68 3687.87,1619.76 3783.86,1715.75 3783.86,1926.56 3806.91,1949.61 START1.2@3896.06,1949.61
  Bottom Layer w10: v1(3052.76,1668.9) v1(3222.83,1668.9)
STOP1: C2.2 P5.5 R7.2 STOP1.2 U2.17 | length 2175.3
  Top Layer w10: U2.17@2372.94,1129.91 2575.75,1129.91 2765.42,940.24 2837.55,940.24 2980.07,797.72 P5.5@3272.05,797.72 ; P5.5@3272.05,796.93 3391.02,796.93 3505.12,911.02 v1(3505.12,1070.87) ; v1(3505.12,1185.04) 3505.12,1327.95 3555.59,1378.43 3682.28,1378.43 3682.68,1378.82 3825.28,1378.82 STOP1.2@3896.06,1449.61
  Bottom Layer w10: v1(3505.12,1070.87) v1(3505.12,1185.04)
SWCLK: P14.2 U2.11 | length 744.1
  Top Layer w10: U2.11@2290.26,988.17 2290.26,946.75 2295.67,941.34 2352.36,941.34 2421.65,872.05 2421.65,800.79 P14.2@2751.97,470.47 ; P14.2@2751.57,469.29 2751.97,469.69 P14.2@2751.97,470.47 ; P14.2@2752.36,470.08 P14.2@2751.97,470.47
SWDIO: P14.3 U2.12 | length 773.5
  Top Layer w10: U2.12@2309.95,988.17 2338.6,988.17 2441.65,885.12 2441.65,855.98 2827.17,470.47 P14.3@2851.97,470.47
TXD0: P5.7 R12.2 U2.19 | length 1424.7
  Top Layer w10: U2.19@2372.94,1169.28 2592.95,1169.28 2780.34,981.89 3256.22,981.89 P5.7@3272.05,997.72 3324.88,997.72 3377.56,1050.39 3377.56,1126.77 3410.63,1159.84 R12.2@3601.57,1159.84
TXD1: P7.11 R11.1 | length 550.8
  Top Layer w10: P7.11@1164.25,499.39 1396.35,731.5 R11.1@1618.9,731.5
ZB: R4.3 R42.1 ZB1.1 | length 2498.6
  Top Layer w20: R42.1@2383.36,244.08 2440.55,186.89 ZB1.1@2440.55,131.1
  Bottom Layer w10: ZB1.1@2440.55,131.1 2526.38,45.28 3970.15,45.28 4389.76,464.89 4389.76,598.08 4369.81,618.03 R4.3@4327.83,618.03
pads on no net: R4.4 R4.5 R4.6 START1.3 START1.4 STOP1.3 STOP1.4

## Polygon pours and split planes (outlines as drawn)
+15V on Top Layer "Top Layer-No Net" (solid, pour order 102): 142.11,924.13 142.11,510.91 141.46,510.26 435.86,510.26 435.86,668.23 437.17,669.54 432.6,674.11 238.72,674.11 238.72,918.9 234.15,923.47
GND on Top Layer "Bottom Layer-No Net" (solid, remove dead copper, pour order 99): -9,640.94 1215.61,640.94 1237.66,663.38 1262.8,688.97 1262.8,1416.93 1262.8,1685.43 1298,1721.26 1303.8,1727.16 2975.17,1727.16 3717.83,1727.16 3757.28,1767.32 3752.25,1772.44 3752.25,2338.97 4485.24,2338.97 4549.83,2273.23 4533.2,2256.3 4533.2,-192.52 -1.26,-192.52 -46.13,-238.19
PGND on Top Layer "Bottom Layer-No Net" (solid, remove dead copper, pour order 55): 2430.32,2357.09 2683.86,2357.09 2689.76,2357.09 2694.09,2352.76 2694.09,2288.98 2694.09,2269.29 2687.8,2262.99 2685.04,2260.24 2509.45,2260.24 2465.75,2260.24 2430.32,2295.67
PGND on Top Layer "Bottom Layer-No Net" (solid, remove dead copper, pour order 56): 1415.35,2356.69 1629.53,2356.69 1652.76,2356.69 1657.48,2351.97 1658.27,2351.18 1658.27,2265.75 1658.27,2257.48 1652.76,2251.97 1651.57,2250.79 1473.23,2250.79 1456.3,2250.79 1415.35,2291.73
AX on Top Layer "Bottom Layer-No Net" (solid, remove dead copper, pour order 58): 790.55,2587.4 790.55,2474.8 806.69,2458.66 1208.27,2458.66 1218.78,2469.17 1218.78,2605.63 1229.69,2616.54 1232.68,2616.54 1471.26,2616.54 1471.65,2616.93 1471.65,2882.68 1471.65,2904.33 1463.39,2912.6 1046.85,2912.6 994.09,2912.6 981.89,2900.39 948.43,2866.93 948.43,2665.75 948.43,2641.73 923.23,2616.54 914.57,2607.87 807.48,2607.87
AI on Top Layer "Bottom Layer-No Net" (solid, remove dead copper, pour order 63): 1390.59,2600.39 1390.59,2475.2 1398.07,2467.72 1407.52,2458.27 1658.31,2458.27 1689.02,2458.27 1696.1,2465.35 1698.07,2467.32 1698.07,2566.93 1698.07,2590.94 1688.62,2600.39
BX on Top Layer "Bottom Layer-No Net" (solid, remove dead copper, pour order 70): 1884.65,2592.52 1869.29,2592.52 1857.87,2581.1 1853.94,2577.17 1853.94,2476.38 1853.94,2465.75 1864.17,2455.51 1869.68,2450 2144.88,2450 2218.9,2450 2229.13,2460.24 2230.71,2461.81 2230.71,2588.98 2230.71,2612.99 2242.91,2625.2 2247.64,2629.92 2351.18,2629.92 2472.83,2629.92 2487.01,2644.09 2495.28,2652.36 2495.28,2870.87 2495.28,2896.06 2479.13,2912.2 2477.17,2914.17 2186.61,2914.17 2050.39,2914.17 2040.16,2903.94 2018.11,2881.89 2018.11,2652.36 2018.11,2618.11 1992.13,2592.13
BI on Top Layer "Bottom Layer-No Net" (solid, remove dead copper, pour order 74): 2386.22,2607.09 2374.02,2594.88 2374.02,2506.3 2374.02,2479.13 2383.86,2469.29 2605.91,2469.29 2701.57,2469.29 2708.27,2475.98 2714.17,2481.89 2714.17,2607.09
CX on Top Layer "Bottom Layer-No Net" (solid, remove dead copper, pour order 78): 2872.44,2614.96 2863.78,2606.3 2863.78,2525.59 2863.78,2463.39 2868.9,2458.27 2871.65,2455.51 3154.33,2455.51 3242.52,2455.51 3253.15,2466.14 3264.57,2477.56 3264.57,2548.03 3264.57,2598.43 3281.89,2615.75 3291.34,2625.2 3516.14,2625.2 3531.89,2625.2 3540.55,2633.86 3540.94,2634.25 3540.94,2883.86 3540.94,2895.28 3527.17,2909.06 3523.23,2912.99 3242.91,2912.99 3055.12,2912.99 3045.67,2903.54 3032.68,2890.55 3032.68,2721.26 3032.68,2625.98 3021.65,2614.96
CI on Top Layer "Bottom Layer-No Net" (solid, remove dead copper, pour order 81): 3418.5,2598.43 3418.5,2481.1 3418.5,2474.02 3426.38,2466.14 3427.95,2464.57 3672.83,2464.57 3734.25,2464.57 3741.73,2472.05 3743.31,2473.62 3743.31,2573.23 3743.31,2576.77 3721.65,2598.43
+48V on Top Layer "Bottom Layer-No Net" (solid, remove dead copper, pour order 84): 312.6,3216.14 289.76,3193.31 289.76,2801.57 289.76,2741.73 259.45,2711.42 258.66,2710.63 183.07,2710.63 175.98,2710.63 151.57,2686.22 147.64,2682.28 147.64,2607.48 147.64,2531.1 156.3,2522.44 210.63,2468.11 516.14,2468.11 581.1,2468.11 608.66,2495.67 608.66,2607.48 608.66,2611.81 624.02,2627.17 650,2653.15 869.68,2653.15 879.13,2653.15 892.13,2666.14 894.49,2668.5 894.49,2860.24 894.49,2863.39 943.31,2912.2 991.34,2960.24 1922.44,2960.24 3812.6,2960.24 3846.06,2926.77 3906.3,2866.54 4214.17,2866.54 4218.11,2866.54 4259.45,2907.87 4261.81,2910.24 4261.81,3271.26
+48V on Top Layer "Bottom Layer-No Net" (solid, remove dead copper, pour order 85): 289.76,3192.81 289.76,3248.82 289.37,3249.21 352.36,3312.2 2944.49,3312.2 4142.42,3312.2 4261.81,3192.81 4261.81,3085.43 337.01,3085.43 289.76,3132.68
+48V on Top Layer "Bottom Layer-No Net" (solid, remove dead copper, pour order 87): 1632.68,2972.05 1667.32,2937.4 1667.32,2683.73 1667.32,2667.72 1683.86,2651.18 1686.22,2648.82 1970.87,2648.82 1979.13,2657.09 1979.13,2922.44 2035.04,2978.35 2011.42,3001.97 1648.82,3001.97
+48V on Top Layer "Bottom Layer-No Net" (solid, remove dead copper, pour order 86): 2643.31,2965.35 2677.95,2930.71 2677.95,2677.03 2677.95,2661.02 2694.49,2644.49 2696.85,2642.13 2981.5,2642.13 2989.76,2650.39 2989.76,2915.75 3045.67,2971.65 3022.05,2995.28 2659.45,2995.28
GND on Top Layer "Bottom Layer-No Net" (solid, remove dead copper, pour order 89): 702.34,1560.52 702.34,1417.06 702.34,1363.06 711.1,1351.06 714.68,1346.15 902.86,1346.15 902.86,1595.43 899.68,1599.79 886.55,1617.79 702.34,1617.79
GND on Top Layer "Bottom Layer-No Net" (solid, remove dead copper, pour order 91): 3772.55,1804.07 873.73,1804.07 824.91,1852.89 792.63,1885.18 792.63,2079.67 794.2,2079.67 819.4,2104.86 827.67,2113.13 1691.44,2113.13 3770.18,2113.13 3787.51,2095.81 3807.19,2076.12 3807.19,1865.89
PGND on Top Layer "Bottom Layer-No Net" (solid, remove dead copper, pour order 92): 3479.53,2370.47 3479.53,2260.24 3492.91,2246.85 3496.06,2243.7 3718.9,2243.7 3725.98,2243.7 3742.91,2260.63 3743.31,2261.02 3743.31,2370.87
PGND on Top Layer "Bottom Layer-No Net" (solid, remove dead copper, pour order 93): 3851.97,2623.23 3851.97,2456.69 3883.46,2425.2 3884.25,2425.98 4235.04,2425.98 4235.04,2602.76 4255.51,2623.23
PGND on Top Layer "Bottom Layer-No Net" (solid, remove dead copper, pour order 95): 3884.25,2425.98 3884.65,2426.38 4578.35,2426.38 4578.35,2791.34 4555.51,2814.17 4554.72,2813.39 4083.46,2813.39 3831.89,2813.39 3805.51,2787.01 3798.03,2779.53 3798.03,2475.2
PGND on Top Layer "Bottom Layer-No Net" (solid, remove dead copper, pour order 98): 575.59,2414.96 575.59,2218.9 594.09,2200.39 594.49,2200 689.76,2200 720.08,2200 730.32,2210.24 731.89,2211.81 731.89,2367.72 731.89,2406.3 717.72,2420.47 714.17,2424.02 587.4,2424.02
+5V on Top Layer "Bottom Layer-No Net" (solid, remove dead copper, pour order 73): 644.88,410.24 640.55,405.91 640.55,248.03 640.55,139.76 650.39,129.92 655.91,124.41 833.86,124.41 872.83,124.41 877.17,128.74 889.37,140.94 889.37,347.64 889.37,406.3 854.72,440.94 843.31,452.36 703.94,452.36 662.99,452.36 644.88,434.25
GND on Top Layer "Top Layer-No Net" (solid, pour order 61): 25.27,2937.8 25.27,1662.89 22.44,1660.14 353.22,1660.14 884.57,1660.14 886.19,1661.71 781.86,1763.2 781.86,2112.51 589.78,2112.51 553.39,2147.92 551.37,2149.88 551.37,2398.49 550.15,2398.49 499.2,2448.05 494.35,2452.77 204.41,2452.77 130.01,2525.15 128.79,2526.33 128.79,2694.7 134.45,2694.7 162.76,2722.23 167.61,2726.95 254.55,2726.95 254.55,2727.74 267.09,2739.93 267.09,2938.98
DM_IN on Top Layer "Top Layer-No Net" (solid, pour order 69): 23.23,1632.28 407.09,1632.28 407.87,1631.5 407.87,1475.98 25.2,1475.98 22.44,1478.74
GND on Top Layer "Top Layer-No Net" (solid, pour order 77): 672.44,918.11 882.28,918.11 882.68,917.72 882.68,693.7 882.68,651.97 881.89,652.76 669.68,652.76
NetCF1_1 on Top Layer "Top Layer-No Net" (solid, pour order 83): 461.16,1521.72 461.71,1522.27 665.47,1522.27 665.47,1393.62 664.91,1393.06 462.26,1393.06
+15V on Top Layer "Bottom Layer-No Net" (solid, remove dead copper, pour order 60): 145.66,924.1 318,924.1 320.48,921.75 353.49,890.42 353.49,741.65 353.49,647.96 346.34,641.17 344.96,639.86 204.72,639.86
NetCF2_2 on Top Layer "Bottom Layer-No Net" (solid, remove dead copper, pour order 62): 385.53,1004.94 385.53,725.81 392.59,719.09 405.38,706.91 443.8,706.91 641.55,706.91 649.05,714.05 649.05,785.51 649.05,997.65 641.39,1004.94
NetCF1_1 on Top Layer "Bottom Layer-No Net" (solid, remove dead copper, pour order 66): 462.21,1457.5 448.69,1443.98 413.41,1443.98 413.41,1361.88 417.7,1357.59 423.96,1351.33 641.91,1351.33 676.86,1351.33 680.82,1355.29 680.49,1355.62 680.49,1514.21 680.49,1520.31 675.5,1525.3 675.39,1525.41 635.88,1525.41 467.88,1525.41 461.19,1518.72
GND on Top Layer "Bottom Layer-No Net" (solid, remove dead copper, pour order 68): 797.28,2062.31 756.61,2102.98 733.01,2102.98 733.01,2026.98 726.2,2020.17 712.59,2006.56 712.59,1766.36 712.59,1761.55 750.31,1723.83 753.52,1720.62 823.85,1720.62 823.85,2035.74 797.28,2062.31
GND on Bottom Layer "Bottom Layer-No Net" (solid, remove dead copper, pour order 101): 825.59,2113.39 576.77,2113.39 558.27,2113.39 541.73,2096.85 529.92,2085.04 529.92,1912.99 575.98,1912.99 735.04,1753.94 741.34,1747.64 848.82,1747.64 848.82,1839.37 854.72,1845.28
GND on Bottom Layer "Bottom Layer-No Net" (solid, remove dead copper, pour order 100): 18.66,665.16 20.22,666.73 1219.75,666.73 1219.75,668.7 1264.67,713.98 1264.67,1712.4 1264.67,1719.09 1296.69,1751.38 1301.77,1756.5 3583.25,1756.5 3807.06,1756.5 3830.89,1780.51 3849.63,1799.41 3849.63,2087.2 4535.52,2087.2 4546.85,2075.79 4524.98,2053.74 4524.98,-112.01 -66.49,-112.01 -98.13,-143.9
AX on Bottom Layer "Bottom Layer-No Net" (solid, remove dead copper, pour order 57): 788.82,2587.4 788.82,2474.8 804.96,2458.66 1206.54,2458.66 1217.05,2469.17 1217.05,2605.63 1227.95,2616.54 1230.94,2616.54 1469.53,2616.54 1469.92,2616.93 1469.92,2882.68 1469.92,2904.33 1461.65,2912.6 1045.12,2912.6 992.36,2912.6 980.16,2900.39 946.69,2866.93 946.69,2665.75 946.69,2641.73 921.5,2616.54 912.83,2607.87 805.75,2607.87
AI on Bottom Layer "Bottom Layer-No Net" (solid, remove dead copper, pour order 59): 1390.55,2600.39 1390.55,2475.2 1398.03,2467.72 1407.48,2458.27 1658.27,2458.27 1688.98,2458.27 1696.06,2465.35 1698.03,2467.32 1698.03,2566.93 1698.03,2590.94 1688.58,2600.39
AX on Bottom Layer "Bottom Layer-No Net" (solid, remove dead copper, pour order 65): 1206.54,2458.66 1206.93,2458.27 1331.1,2458.27 1359.45,2458.27 1366.54,2465.35 1369.29,2468.11 1369.29,2616.54 1369.29,2639.37 1349.61,2659.06 1185.83,2659.06
BX on Bottom Layer "Bottom Layer-No Net" (solid, remove dead copper, pour order 67): 1885.04,2592.91 1869.69,2592.91 1858.27,2581.5 1854.33,2577.56 1854.33,2476.77 1854.33,2466.14 1864.57,2455.91 1870.08,2450.39 2145.28,2450.39 2219.29,2450.39 2229.53,2460.63 2231.1,2462.2 2231.1,2589.37 2231.1,2613.39 2243.31,2625.59 2248.03,2630.31 2351.57,2630.31 2473.23,2630.31 2487.4,2644.49 2495.67,2652.76 2495.67,2871.26 2495.67,2896.46 2479.53,2912.6 2477.56,2914.57 2187.01,2914.57 2050.79,2914.57 2040.55,2904.33 2018.5,2882.28 2018.5,2652.76 2018.5,2618.5 1992.52,2592.52
BI on Bottom Layer "Bottom Layer-No Net" (solid, remove dead copper, pour order 71): 2385.47,2606.69 2373.27,2594.49 2373.27,2505.91 2373.27,2478.74 2383.11,2468.9 2605.16,2468.9 2700.83,2468.9 2707.52,2475.59 2713.43,2481.5 2713.43,2606.69
BX on Bottom Layer "Bottom Layer-No Net" (solid, remove dead copper, pour order 75): 2219.29,2450.39 2347.64,2450.39 2355.51,2458.27 2358.27,2461.02 2358.27,2646.06 2228.35,2646.06 2222.05,2639.76
CX on Bottom Layer "Bottom Layer-No Net" (solid, remove dead copper, pour order 76): 2872.83,2615.75 2864.17,2607.09 2864.17,2526.38 2864.17,2464.17 2869.29,2459.06 2872.05,2456.3 3154.72,2456.3 3242.91,2456.3 3253.54,2466.93 3264.96,2478.35 3264.96,2548.82 3264.96,2599.21 3282.28,2616.54 3291.73,2625.98 3516.54,2625.98 3532.28,2625.98 3540.94,2634.65 3541.34,2635.04 3541.34,2884.65 3541.34,2896.06 3527.56,2909.84 3523.62,2913.78 3243.31,2913.78 3055.51,2913.78 3046.06,2904.33 3033.07,2891.34 3033.07,2722.05 3033.07,2626.77 3022.05,2615.75
CI on Bottom Layer "Bottom Layer-No Net" (solid, remove dead copper, pour order 79): 3418.11,2598.03 3418.11,2480.71 3418.11,2473.62 3425.98,2465.75 3427.56,2464.17 3672.44,2464.17 3733.86,2464.17 3741.34,2471.65 3742.91,2473.23 3742.91,2572.83 3742.91,2576.38 3721.26,2598.03
PGND on Bottom Layer "Bottom Layer-No Net" (solid, remove dead copper, pour order 88): 568.5,2345.13 568.5,2271.82 568.5,2210.41 611.02,2170.22 644.49,2138.58 1381.1,2138.58 3765.75,2138.58 3781.89,2153.84 3801.57,2172.45 3801.57,2293.4 3801.57,2376.76 3786.61,2390.91 3765.75,2410.63 696.85,2410.63
+48V on Bottom Layer "Bottom Layer-No Net" (solid, remove dead copper, pour order 82): 311.81,3216.93 288.98,3194.09 288.98,2802.36 288.98,2742.52 258.66,2712.2 257.87,2711.42 182.28,2711.42 175.2,2711.42 150.79,2687.01 146.85,2683.07 146.85,2608.27 146.85,2531.89 155.51,2523.23 209.84,2468.9 515.35,2468.9 580.31,2468.9 607.87,2496.46 607.87,2608.27 607.87,2612.6 623.23,2627.95 649.21,2653.94 868.9,2653.94 878.35,2653.94 891.34,2666.93 893.7,2669.29 893.7,2861.02 893.7,2864.17 942.52,2912.99 990.55,2961.02 1921.65,2961.02 3811.81,2961.02 3845.28,2927.56 3905.51,2867.32 4213.39,2867.32 4217.32,2867.32 4258.66,2908.66 4261.02,2911.02 4261.02,3272.05
GND on Bottom Layer "Bottom Layer-No Net" (solid, remove dead copper, pour order 90): 3770.47,1804.33 871.65,1804.33 822.83,1853.15 790.55,1885.43 790.55,2079.92 792.13,2079.92 817.32,2105.12 825.59,2113.39 1689.37,2113.39 3768.11,2113.39 3785.43,2096.06 3805.12,2076.38 3805.12,1866.14
PGND on Bottom Layer "Bottom Layer-No Net" (solid, remove dead copper, pour order 94): 3765.75,2138.58 4558.27,2138.58 4558.27,2813.26 4563.39,2818.11 4559.06,2814.01 4225.2,2814.01 3833.46,2814.01 3783.86,2767.04 3782.28,2765.55 3782.28,2458.78 3782.28,2207.17 3765.75,2191.51
+48V on Bottom Layer "Bottom Layer-No Net" (solid, remove dead copper, pour order 96): 1616.93,2963.39 1641.34,2963.39 1665.75,2938.98 1667.32,2937.4 1667.32,2915.75 1667.32,2684.53 1703.03,2648.82 1703.82,2648.03 1970.87,2648.03 1979.92,2657.09 1980.32,2657.48 1980.32,2904.72 1980.32,2923.23 2030.71,2973.62 1980.71,3023.62 1647.24,3023.62
+48V on Bottom Layer "Bottom Layer-No Net" (solid, remove dead copper, pour order 97): 2606.3,2975.59 2633.07,2975.59 2677.95,2930.71 2677.95,2675.98 2677.95,2666.54 2701.57,2642.91 2702.76,2641.73 2831.5,2641.73 2980.71,2641.73 2989.76,2650.79 2989.76,2807.87 2989.76,2915.75 3055.12,2981.1 3027.95,3008.27 2868.9,3008.27
GND on Bottom Layer "Top Layer-No Net" (solid, pour order 64): 25.59,2937.8 25.59,1670.01 24.02,1668.44 30.71,1661.77 866.93,1661.77 777.56,1750.84 776.77,1751.63 741.34,1751.63 535.04,1957.23 535.04,2189.92 535.04,2397.09 533.86,2398.27 486.22,2445.75 206.3,2445.75 124.02,2527.76 124.8,2528.54 124.8,2760.44 124.8,2697.27 156.69,2729.05 156.69,2729.44 246.46,2729.44 248.43,2731.4 257.87,2740.82 257.87,2937.8 23.62,2937.8
DM_IN on Bottom Layer "Top Layer-No Net" (solid, pour order 72): 25.2,1629.53 402.76,1629.53 402.76,1480.31 403.54,1479.53 25.98,1479.53
GND on Bottom Layer "Top Layer-No Net" (solid, pour order 80): 681.1,914.57 877.95,914.57 878.74,915.35 877.17,913.78 877.17,657.87 676.77,657.87 675.2,656.3
PGND on Bottom Solder "Bottom Layer-No Net" (solid): 4140.94,3031.1 4140.94,2890.16 4127.56,2876.77 4127.17,2876.38 3925.59,2876.38 3920.87,2876.38 3798.03,2999.21 3780.71,3016.54 3780.71,3100.39
PGND on Bottom Solder "Bottom Layer-No Net" (solid, pour order 48): 634.65,2418.9 591.73,2375.98 591.73,2219.29 591.73,2200 624.8,2166.93 633.86,2157.87 803.94,2157.87 1433.46,2157.87 1518.11,2242.52 1521.65,2246.06 1617.72,2246.06 1617.72,2236.61 1692.52,2161.81 1693.31,2161.02 2441.73,2161.02 2455.91,2161.02 2545.28,2250.39 2548.03,2253.15 2629.53,2253.15 2637.4,2253.15 2661.02,2229.53 2717.72,2172.83 3426.77,2172.83 3519.68,2172.83 3581.89,2235.04 3585.04,2238.19 3662.99,2238.19 3662.99,2237.01 3726.38,2173.62 4472.44,2173.62 4472.44,2731.1 4424.02,2779.53 4412.6,2790.94 3924.8,2790.94 3841.34,2790.94 3810.63,2760.24 3802.36,2751.97 3802.36,2464.96 3802.36,2462.99 3745.28,2405.91 3732.68,2418.5 675.59,2418.5
+48V on Bottom Solder "Bottom Layer-No Net" (solid): 313.39,3180.71 313.39,2803.94 313.39,2719.29 292.13,2698.03 274.41,2680.32 235.43,2680.32 214.96,2680.32 196.85,2662.2 191.73,2657.09 191.73,2583.46 191.73,2543.7 205.12,2530.32 237.4,2498.03 344.09,2498.03 552.76,2498.03 572.83,2518.11 580.71,2525.98 580.71,2590.55 580.71,2636.22 611.42,2666.93 628.35,2683.86 838.19,2683.86 864.96,2683.86 878.35,2697.24 878.35,2859.45 878.35,2888.19 967.32,2977.17 980.31,2990.16 1639.37,2990.16 1647.24,2990.16 1683.86,2953.54 1685.04,2952.36 1685.04,2758.66 1685.04,2738.98 1749.61,2674.41 1948.03,2674.41 1953.54,2674.41 1966.54,2687.4 1966.54,2910.24 1966.54,2937.01 2000.79,2971.26 2014.96,2985.43 2668.5,2985.43 2668.5,2982.68 2704.72,2946.46 2702.36,2944.09 2702.36,2718.9 2702.36,2715.35 2756.3,2661.42 2761.02,2666.14 2960.63,2666.14 2960.63,2919.69 3025.2,2984.25 3043.7,3002.76 4012.99,3002.76 4112.6,3002.76 4133.86,3024.02 4140.94,3031.1 4140.94,3197.64 323.62,3197.64 313.39,3187.4
CX on Bottom Solder "Bottom Layer-No Net" (solid): 3064.17,2896.46 3046.85,2879.13 3046.85,2790.16 3046.85,2625.59 3024.41,2603.15 3024.02,2602.76 2935.04,2602.76 2881.89,2602.76 2874.41,2595.28 2871.65,2592.52 2871.65,2499.21 2871.65,2474.8 2880.31,2466.14 2881.89,2464.57 3216.14,2464.57 3237.8,2464.57 3249.61,2476.38 3253.94,2480.71 3253.94,2592.13 3253.94,2608.27 3281.1,2635.43 3283.86,2638.19 3519.29,2638.19 3524.02,2638.19 3530.71,2644.88 3531.5,2645.67 3531.5,2766.93 3531.5,2881.5 3516.14,2896.85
